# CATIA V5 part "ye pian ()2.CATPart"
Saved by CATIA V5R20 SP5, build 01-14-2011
Part number: 01
Bounding box of the stored display mesh (mm): x 0 to 148.055, y -45.058 to 54.981, z -2 to 2
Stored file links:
  E:\姜浩然03.08\创意作品\ye pian ()2.CATPart
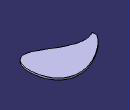
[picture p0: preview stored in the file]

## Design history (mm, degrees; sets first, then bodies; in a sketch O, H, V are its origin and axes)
Body1 (main body)
  Sketch1 on xy-plane, origin (0, 0, 0), H (1, 0, 0), V (0, 1, 0)
    spline S1 through (0, 0) (31.2545, 30.6484) (138.3395, 30.6484) (135.7777, -41.3753) (59.4348, -14.558) (0, -10.4715)
    spline S2 through (0, -10.4715) (0, 0)
    point P1 (0, 0)
    point P2 (0, -10.4715)
    point P3 (0, -10.4715)
    point P4 (0, 0)
    coincidence: P1 O, P2 V, P3 P2, P4 O
  Pad1: profile Sketch1, direction (0, 0, 1), length 1, mirrored extent
  Thickness1: Face end face of Pad1, Thickness 1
